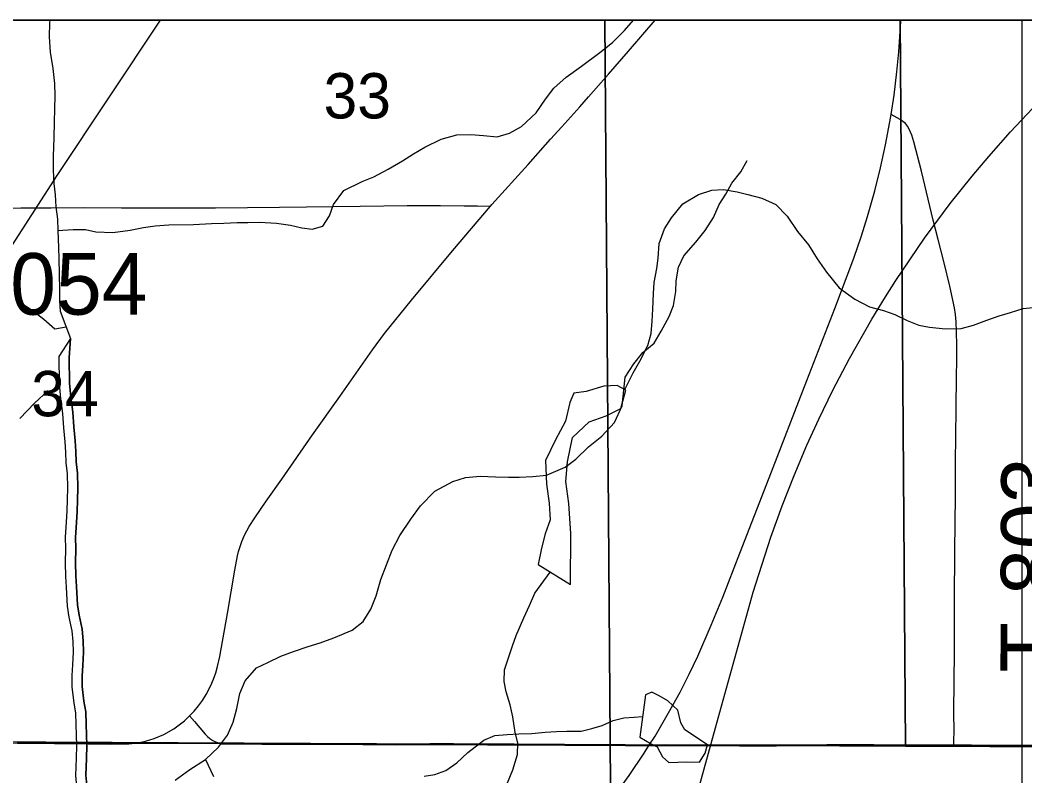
# Model space of a CAD drawing. Extents: x 0 to 34, y 0 to 22.
# Drawn here: x 15.155 to 16.083, y 20.202 to 20.9 of the extents above; entities that cross this region are included whole.
import ezdxf

# ---------------------------------------------------------------- set-up
doc = ezdxf.new("R2010")
doc.units = 0
for name, color, linetype in [('Default', 7, 'Continuous'), ('GM_X_County_Road', 7, 'Continuous'), ('GM_X_Major_River', 7, 'Continuous'), ('GM_X_Minor_Lake', 7, 'Continuous'), ('GM_X_Minor_River', 7, 'Continuous'), ('GM_X_Rail_Line', 7, 'Continuous'), ('GM_X_Section', 7, 'Continuous'), ('GM_X_Section_Text', 7, 'Continuous'), ('GM_X_State_Route', 7, 'Continuous'), ('GM_X_Township_Road', 7, 'Continuous'), ('GM_X_Township_Road_Text', 7, 'Continuous'), ('GM_X_US_Shield', 7, 'Continuous'), ('SH_Data', 7, 'Continuous')]:
    doc.layers.add(name, color=color, linetype=linetype)

msp = doc.modelspace()

# ---------------------------------------------------------------- linework, layer by layer
at = {"layer": 'Default'}
for points in [[(15.69541, 20.9), (14.69598, 20.9), (14.70213, 20.07058), (14.8579, 20.06976), (15.70156, 20.06848)], [(16.0808, 20.06936), (16.0808, 20.9), (15.69541, 20.9), (15.70156, 20.06848), (15.86074, 20.06919)]]:
    msp.add_lwpolyline(points, close=True, dxfattribs=at)
at = {"layer": 'GM_X_County_Road'}
for points in [[(15.58964, 20.72819), (15.591, 20.72984), (15.62437, 20.76681), (15.6451, 20.78994), (15.65549, 20.80146), (15.6721, 20.81987), (15.68034, 20.82916), (15.69875, 20.85018), (15.71704, 20.87132), (15.7418, 20.9)], [(15.31188, 20.25773), (15.31278, 20.2586), (15.31612, 20.26202), (15.32017, 20.26682), (15.32384, 20.27192), (15.32714, 20.27725), (15.33144, 20.28561), (15.3339, 20.29139), (15.33599, 20.29729), (15.3377, 20.30332), (15.33974, 20.31246), (15.34694, 20.35222), (15.35371, 20.39202), (15.35613, 20.40537), (15.35703, 20.40931), (15.3581, 20.41302), (15.36007, 20.41853), (15.36246, 20.42436), (15.36698, 20.43259), (15.37221, 20.44052), (15.38264, 20.45591), (15.39701, 20.47619), (15.42536, 20.51701), (15.45057, 20.55242), (15.48075, 20.59571), (15.4917, 20.61073), (15.51674, 20.64153), (15.55473, 20.68692), (15.58964, 20.72819)], [(15.25569, 20.2318), (15.264, 20.23274), (15.27118, 20.2343), (15.27908, 20.23679), (15.28812, 20.24043), (15.29727, 20.24563), (15.30714, 20.25311), (15.31188, 20.25773)], [(15.08073, 20.23177), (15.08472, 20.23234), (15.09084, 20.23283), (15.10633, 20.23302), (15.15291, 20.23247), (15.18707, 20.23214), (15.21813, 20.23183), (15.23863, 20.23152), (15.25569, 20.2318)]]:
    msp.add_lwpolyline(points, dxfattribs=at)
at = {"layer": 'GM_X_Major_River'}
for points in [[(15.20192, 20.60619), (15.1911, 20.58937), (15.19131, 20.56429), (15.19256, 20.55061), (15.19457, 20.53694), (15.19544, 20.52364), (15.19669, 20.51072), (15.19715, 20.50122), (15.19761, 20.49134), (15.19883, 20.48109), (15.19894, 20.46816), (15.19865, 20.45713), (15.19836, 20.44687), (15.19768, 20.4366), (15.19704, 20.42253), (15.19712, 20.41226), (15.19685, 20.39896), (15.19734, 20.38641), (15.1978, 20.37653), (15.1987, 20.35905), (15.20031, 20.3488), (15.20307, 20.33627), (15.20391, 20.3264), (15.20437, 20.31652), (15.20371, 20.30473), (15.20303, 20.29484), (15.20312, 20.28419), (15.20476, 20.26976), (15.20636, 20.26027), (15.20683, 20.24963), (15.20691, 20.23974), (15.20737, 20.23024), (15.20708, 20.21845), (15.20646, 20.20248), (15.20771, 20.18919)], [(15.21718, 20.19053), (15.21603, 20.20274), (15.21663, 20.21815), (15.21693, 20.23036), (15.21646, 20.24001), (15.21638, 20.24987), (15.21588, 20.26127), (15.21422, 20.27109), (15.21267, 20.28477), (15.21259, 20.29455), (15.21325, 20.30413), (15.21394, 20.31647), (15.21344, 20.32703), (15.21253, 20.33771), (15.2097, 20.35057), (15.20822, 20.36004), (15.20734, 20.377), (15.20688, 20.38682), (15.20641, 20.39904), (15.20668, 20.41221), (15.20659, 20.42235), (15.20722, 20.43607), (15.2079, 20.44642), (15.2082, 20.45687), (15.20849, 20.46808), (15.20838, 20.48169), (15.20713, 20.49213), (15.20669, 20.50167), (15.20622, 20.51141), (15.20496, 20.52441), (15.20408, 20.53795), (15.20205, 20.55174), (15.20085, 20.56476), (15.20066, 20.58815), (15.20192, 20.60619)], [(15.20192, 20.60619), (15.20066, 20.58815), (15.20085, 20.56476), (15.20205, 20.55174), (15.20408, 20.53795), (15.20496, 20.52441), (15.20622, 20.51141), (15.20669, 20.50167), (15.20713, 20.49213), (15.20838, 20.48169), (15.20849, 20.46808), (15.2082, 20.45687), (15.2079, 20.44642), (15.20722, 20.43607), (15.20659, 20.42235), (15.20668, 20.41221), (15.20641, 20.39904), (15.20688, 20.38682), (15.20734, 20.377), (15.20822, 20.36004), (15.2097, 20.35057), (15.21253, 20.33771), (15.21344, 20.32703), (15.21394, 20.31647), (15.21325, 20.30413), (15.21259, 20.29455), (15.21267, 20.28477), (15.21422, 20.27109), (15.21588, 20.26127), (15.21638, 20.24987), (15.21646, 20.24001), (15.21693, 20.23036), (15.21663, 20.21815), (15.21603, 20.20274), (15.21718, 20.19053)]]:
    msp.add_lwpolyline(points, dxfattribs=at)
at = {"layer": 'GM_X_Minor_Lake'}
for points in [[(15.66355, 20.37886), (15.66392, 20.426), (15.66217, 20.45374), (15.65934, 20.47387), (15.66071, 20.49212), (15.66546, 20.51459), (15.68092, 20.52915), (15.69645, 20.53459), (15.71007, 20.54153), (15.71487, 20.55829), (15.70686, 20.5628), (15.69433, 20.56194), (15.67803, 20.55726), (15.66665, 20.55565), (15.66292, 20.54688), (15.65888, 20.52975), (15.6499, 20.51257), (15.64057, 20.49349), (15.64151, 20.47145), (15.64393, 20.45398), (15.64482, 20.43878), (15.64037, 20.42582), (15.63668, 20.41249), (15.63376, 20.39726)], [(15.63376, 20.39726), (15.66355, 20.37886)], [(15.72755, 20.23793), (15.73824, 20.23193), (15.74358, 20.22892), (15.7486, 20.21984), (15.75434, 20.21456), (15.77105, 20.21506), (15.78283, 20.21477), (15.78808, 20.22317), (15.7903, 20.23079), (15.76929, 20.2447), (15.76544, 20.25114), (15.76268, 20.2629), (15.75349, 20.27158), (15.74548, 20.27608), (15.73861, 20.27945), (15.73293, 20.27713)], [(15.73293, 20.27713), (15.72755, 20.23793)]]:
    msp.add_lwpolyline(points, dxfattribs=at)
at = {"layer": 'GM_X_Minor_River'}
for points in [[(15.1826, 20.9), (15.18247, 20.89762), (15.1822, 20.88469), (15.18307, 20.87025), (15.18548, 20.85544), (15.18711, 20.84139), (15.18721, 20.82999), (15.18693, 20.8182), (15.18665, 20.80565), (15.18639, 20.7912), (15.18577, 20.77447), (15.18587, 20.76155), (15.18636, 20.74901), (15.18758, 20.73875), (15.18843, 20.72773), (15.18967, 20.71634), (15.19014, 20.7057), (15.19064, 20.69012), (15.19111, 20.67947), (15.19123, 20.66579), (15.19173, 20.65097), (15.19181, 20.6407), (15.19227, 20.6312), (15.20192, 20.60619)], [(15.19014, 20.7057), (15.20419, 20.70656), (15.21558, 20.70665), (15.2251, 20.70444), (15.24106, 20.7038), (15.257, 20.70619), (15.26914, 20.70857), (15.28014, 20.71017), (15.29267, 20.71102), (15.31546, 20.71119), (15.33217, 20.71208), (15.34356, 20.71254), (15.35572, 20.71301), (15.3656, 20.71308), (15.37623, 20.71355), (15.39219, 20.71252), (15.40513, 20.71072), (15.4154, 20.70813), (15.42491, 20.70706), (15.43477, 20.7098), (15.44115, 20.71935), (15.44486, 20.72964), (15.45425, 20.74264), (15.47128, 20.75113), (15.48188, 20.75539), (15.49512, 20.76233), (15.50835, 20.77003), (15.51855, 20.77657), (15.52914, 20.78273), (15.54428, 20.79007), (15.55868, 20.79397), (15.57159, 20.79445), (15.58338, 20.7934), (15.59593, 20.79235), (15.6073, 20.79547), (15.61826, 20.80164), (15.63183, 20.81429), (15.64047, 20.8269), (15.64836, 20.83722), (15.65968, 20.84719), (15.67365, 20.85755), (15.69064, 20.87023), (15.70234, 20.87944), (15.71364, 20.89055), (15.72188, 20.9)], [(15.2986, 20.19826), (15.31219, 20.20824), (15.32655, 20.21747), (15.33861, 20.22859), (15.34688, 20.23967), (15.3521, 20.25188), (15.35541, 20.26445), (15.35834, 20.27815), (15.36318, 20.28998), (15.37372, 20.30184), (15.38394, 20.30686), (15.39604, 20.31265), (15.40779, 20.31692), (15.42142, 20.32158), (15.43241, 20.32508), (15.44491, 20.32974), (15.46195, 20.33671), (15.47214, 20.34477), (15.47926, 20.35622), (15.4841, 20.36843), (15.48853, 20.38367), (15.49374, 20.39701), (15.49895, 20.41073), (15.50606, 20.42409), (15.51619, 20.43938), (15.5252, 20.45161), (15.53839, 20.46501), (15.55503, 20.47388), (15.56678, 20.47777), (15.58006, 20.47901), (15.5945, 20.47835), (15.60628, 20.47806), (15.61616, 20.47813), (15.62869, 20.47861), (15.6416, 20.47984), (15.65864, 20.48719), (15.66845, 20.49449), (15.68013, 20.50598), (15.69259, 20.51596), (15.70426, 20.52859), (15.71135, 20.54385), (15.71275, 20.5583), (15.71417, 20.57048), (15.72205, 20.5827), (15.73032, 20.59303), (15.74089, 20.60185), (15.74725, 20.61292), (15.75474, 20.62629), (15.75883, 20.63658), (15.76101, 20.64952), (15.76131, 20.65941), (15.76348, 20.67197), (15.76833, 20.68227), (15.77925, 20.6949), (15.7879, 20.7056), (15.79577, 20.71783), (15.801, 20.72965), (15.80699, 20.7392), (15.81261, 20.74951), (15.82088, 20.75983), (15.82687, 20.77052)], [(15.71371, 20.55895), (15.72158, 20.57431), (15.72757, 20.585), (15.73505, 20.5995), (15.73799, 20.61055), (15.73904, 20.62196), (15.73971, 20.63299), (15.74035, 20.64744), (15.74102, 20.65771), (15.7432, 20.67065), (15.74464, 20.68017), (15.74566, 20.69386), (15.75049, 20.7072), (15.75686, 20.71751), (15.76739, 20.73052), (15.78176, 20.73899), (15.79426, 20.74288), (15.80489, 20.74372), (15.81745, 20.74154), (15.82735, 20.73895), (15.84029, 20.73562), (15.85326, 20.72963), (15.8636, 20.71907), (15.87322, 20.70469), (15.88358, 20.6926), (15.89128, 20.67973), (15.90012, 20.66726), (15.91164, 20.6529), (15.92616, 20.64236), (15.9399, 20.63524), (15.95284, 20.63191), (15.96313, 20.62819), (15.97457, 20.62257), (15.98525, 20.61847), (15.99514, 20.61664), (16.00997, 20.61485), (16.0244, 20.61533), (16.03577, 20.61846), (16.04827, 20.62312), (16.05964, 20.627), (16.06987, 20.63012), (16.08162, 20.63363), (16.10884, 20.63661)], [(15.19793, 20.61653), (15.1875, 20.61452), (15.1773, 20.6237), (15.16634, 20.63176), (15.15424, 20.63982)], [(15.15489, 20.53212), (15.16846, 20.54629), (15.18127, 20.55817)], [(15.60542, 20.19594), (15.61026, 20.20776), (15.6147, 20.22186), (15.61499, 20.23289), (15.61263, 20.24238), (15.61023, 20.2568), (15.60786, 20.26781), (15.60434, 20.27995), (15.60236, 20.28944), (15.60266, 20.30009), (15.60673, 20.31228), (15.61007, 20.32219), (15.61341, 20.33172), (15.6205, 20.34812), (15.62572, 20.35957), (15.63056, 20.37101), (15.64488, 20.39039)], [(15.52841, 20.20186), (15.53827, 20.20345), (15.54849, 20.20733), (15.5587, 20.21425), (15.56887, 20.22383), (15.58359, 20.23534), (15.59382, 20.2396), (15.60521, 20.24045), (15.61584, 20.2409), (15.62799, 20.24137), (15.64014, 20.24261), (15.65077, 20.24306), (15.66027, 20.24351), (15.67356, 20.24361), (15.68342, 20.24597), (15.69289, 20.2487), (15.70311, 20.25333), (15.71297, 20.25569), (15.72246, 20.25652), (15.73018, 20.25709)], [(15.32655, 20.21747), (15.3339, 20.20156)]]:
    msp.add_lwpolyline(points, dxfattribs=at)
at = {"layer": 'GM_X_Rail_Line'}
for points in [[(18.97704, 20.9), (13.2404, 20.9)], [(15.01329, 19.19028), (15.01014, 19.19836), (15.06033, 19.35767), (15.01937, 19.43771), (15.00255, 19.501), (14.997, 19.61181), (14.99708, 19.69487), (15.00541, 19.73535), (15.01017, 19.77346), (14.99828, 19.87704), (14.9781, 20.30503), (14.97675, 20.37959), (14.99858, 20.4433), (15.03316, 20.51247), (15.08956, 20.60166), (15.18963, 20.75638), (15.28484, 20.9)], [(15.77801, 20.17638), (15.79989, 20.25557), (15.83227, 20.37196), (15.84854, 20.42263), (15.85896, 20.4515), (15.87007, 20.47951), (15.88188, 20.50768), (15.89282, 20.53149), (15.90577, 20.55835), (15.92135, 20.58767), (15.9418, 20.62388), (15.95443, 20.64455), (15.96405, 20.6596), (15.99066, 20.69863), (16.01437, 20.73062), (16.0345, 20.75594), (16.0499, 20.77406), (16.06985, 20.79681), (16.09024, 20.81851)], [(16.09919, 20.23034), (16.06812, 20.23042), (16.03393, 20.23061), (16.0184, 20.23068), (16.01758, 20.23068), (15.94388, 20.23076), (15.90041, 20.23077), (15.8538, 20.23067), (15.81963, 20.23062), (15.79478, 20.23074), (15.78547, 20.23073), (15.7513, 20.23084), (15.7359, 20.23074), (15.72956, 20.2307), (15.71405, 20.23097), (15.65815, 20.23122), (15.61156, 20.23142), (15.58669, 20.23149), (15.55562, 20.23171), (15.53385, 20.23175), (15.5028, 20.23147), (15.47173, 20.23181), (15.422, 20.23207), (15.37847, 20.23205), (15.34744, 20.23236), (15.34118, 20.23236), (15.25547, 20.23235), (15.23842, 20.23206), (15.21791, 20.23238), (15.18686, 20.23269), (15.15269, 20.23302)], [(15.15269, 20.23302), (15.18686, 20.23269), (15.21791, 20.23238), (15.23842, 20.23206), (15.25547, 20.23235), (15.34118, 20.23236), (15.34744, 20.23236), (15.37847, 20.23205), (15.422, 20.23207), (15.47173, 20.23181), (15.5028, 20.23147), (15.53385, 20.23175), (15.55562, 20.23171), (15.58669, 20.23149), (15.61156, 20.23142), (15.65815, 20.23122), (15.71405, 20.23097), (15.72956, 20.2307), (15.7359, 20.23074), (15.7513, 20.23084), (15.78547, 20.23073), (15.79478, 20.23074), (15.81963, 20.23062), (15.8538, 20.23067), (15.90041, 20.23077), (15.94388, 20.23076), (16.01758, 20.23068), (16.0184, 20.23068), (16.03393, 20.23061), (16.06812, 20.23042), (16.09919, 20.23034)]]:
    msp.add_lwpolyline(points, dxfattribs=at)
at = {"layer": 'GM_X_Section'}
msp.add_lwpolyline([(15.97295, 20.22976), (16.12872, 20.22894), (16.12665, 19.21892), (15.1219, 19.23237), (15.11792, 20.23404)], close=True, dxfattribs=at)
at = {"layer": 'GM_X_State_Route'}
for points in [[(15.73611, 20.23019), (15.74169, 20.23905), (15.75424, 20.26048), (15.76476, 20.27949), (15.77324, 20.29606), (15.78121, 20.31289), (15.79366, 20.34134), (15.80431, 20.36719), (15.8201, 20.40772), (15.847, 20.47731), (15.88182, 20.56716), (15.90762, 20.63383), (15.92529, 20.6803), (15.93249, 20.7008), (15.93803, 20.71858), (15.94473, 20.74249), (15.94997, 20.76358), (15.95462, 20.78481), (15.95863, 20.80617), (15.95967, 20.8128), (15.96246, 20.83071), (15.96515, 20.85226), (15.96684, 20.87081), (15.96858, 20.89871), (15.96863, 20.9)], [(15.29811, 19.7412), (15.30838, 19.7523), (15.36354, 19.81136), (15.46747, 19.9227), (15.57769, 20.04093), (15.60508, 20.07064), (15.63488, 20.10232), (15.65991, 20.12993), (15.67826, 20.15101), (15.69009, 20.16537), (15.70332, 20.1826), (15.71786, 20.20273), (15.73177, 20.2233), (15.73611, 20.23019)]]:
    msp.add_lwpolyline(points, dxfattribs=at)
at = {"layer": 'GM_X_Township_Road'}
for points in [[(16.02035, 20.58488), (16.02054, 20.59986), (16.02026, 20.61227), (16.01968, 20.62157), (16.01923, 20.62826), (16.01837, 20.63431), (16.01406, 20.65441), (16.00887, 20.67588), (16.00333, 20.69735), (15.99843, 20.71533), (15.98766, 20.76063), (15.98066, 20.7877), (15.97886, 20.79367), (15.97776, 20.79658), (15.97645, 20.79938), (15.97484, 20.80203), (15.97288, 20.80441), (15.9706, 20.80651), (15.96804, 20.80829), (15.96532, 20.80976), (15.95967, 20.8128)], [(14.96539, 20.72529), (14.98218, 20.72572), (15.00848, 20.72602), (15.05365, 20.72612), (15.11569, 20.72636), (15.15601, 20.72654), (15.18392, 20.72675), (15.21493, 20.72702), (15.24904, 20.7267), (15.27696, 20.72656), (15.31891, 20.72674)], [(15.31891, 20.72674), (15.33589, 20.72681), (15.39482, 20.72729), (15.46926, 20.72828), (15.51267, 20.72897), (15.54367, 20.72883), (15.56535, 20.72862), (15.5777, 20.72859), (15.58964, 20.72819)], [(16.0182, 20.33994), (16.01812, 20.36376), (16.01858, 20.41036), (16.0191, 20.46039), (16.01922, 20.4916), (16.01976, 20.54083), (16.02019, 20.5719), (16.02035, 20.58488)], [(16.01779, 20.23013), (16.01781, 20.23592), (16.01783, 20.2426), (16.01774, 20.26124), (16.01834, 20.31716), (16.01821, 20.33579), (16.0182, 20.33994)], [(15.31188, 20.25773), (15.31627, 20.25256), (15.32624, 20.24081), (15.32838, 20.23864), (15.33066, 20.23667), (15.33313, 20.235), (15.33579, 20.23367), (15.33862, 20.23272), (15.34139, 20.23181)], [(15.34139, 20.23181), (15.34765, 20.23181), (15.37868, 20.2315), (15.42221, 20.23152), (15.47195, 20.23126), (15.50301, 20.23092), (15.53407, 20.23121), (15.55583, 20.23116), (15.58691, 20.23094), (15.61177, 20.23087), (15.65836, 20.23067), (15.71426, 20.23042), (15.72977, 20.23015), (15.73611, 20.23019)], [(15.73611, 20.23019), (15.75151, 20.23029), (15.78568, 20.23018), (15.79499, 20.23019), (15.81984, 20.23007), (15.85402, 20.23012), (15.90062, 20.23022), (15.94409, 20.23021), (16.01779, 20.23013)], [(16.01779, 20.23013), (16.01861, 20.23013), (16.03415, 20.23006), (16.06833, 20.22987), (16.0994, 20.22979), (16.12426, 20.22997), (16.12873, 20.22997)]]:
    msp.add_lwpolyline(points, dxfattribs=at)
at = {"layer": 'GM_X_US_Shield'}
for points in [[(15.96798, 20.9), (14.96821, 20.9), (14.95647, 20.23484), (15.11792, 20.23404), (15.97295, 20.22976)], [(16.9674, 20.9), (15.96798, 20.9), (15.97295, 20.22976), (16.12872, 20.22894), (16.97238, 20.22766)]]:
    msp.add_lwpolyline(points, close=True, dxfattribs=at)
at = {"layer": 'SH_Data'}
msp.add_line((13.2404, 20.9), (20.0404, 20.9), dxfattribs=at)

# ---------------------------------------------------------------- texts
at = {"layer": 'GM_X_Section_Text'}
for s, p in [('33', (15.43554, 20.80922)), ('34', (15.16555, 20.53421))]:
    msp.add_text(s, height=0.041856, rotation=0.00001, dxfattribs=at).set_placement(p)
at = {"layer": 'GM_X_Township_Road_Text'}
for s, rotation, p in [('T-1054', 0.00001, (15.0322, 20.62805)), ('T-803', 89.72051, (16.11749, 20.29743))]:
    msp.add_text(s, height=0.056818, rotation=rotation, dxfattribs=at).set_placement(p)

doc.saveas('drawing.dxf')
